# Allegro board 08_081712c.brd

Outline 415.29 x 196.85 mm; copper layers: TOP, L2_GND, L3_SIG, L4_GND, L5_PWR, L6_PWR, L7_GND, L8_SIG, L9_GND, BOTTOM. Coordinates in mm from the lower left corner of the outline.
Outline path: rectangle 0,0 415.29,196.85

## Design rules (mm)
constraint set DEFAULT: min track width 0.127
net group _N2180: nets _N2180 _N2453
net group DP__N689: nets _N689 _N710
net group DP__N697: nets _N697 _N701
net group DP_A1N_FB: nets _N582 A1N_FB
net group DP_A2N_FB: nets _N588 A2N_FB
net group DP_A3N_FB: nets _N570 A3N_FB
net group DP_A4N_FB: nets _N696 A4N_FB
net group DP_A5N_FB: nets _N702 A5N_FB
net group DP_A6N_FB: nets _N708 A6N_FB
net group DP_A7N_FB: nets _N690 A7N_FB
net group DP_AIN1_BUF: nets _N558 _N560
net group DP_AIN2_BUF: nets _N556 _N563
net group DP_AIN3_BUF: nets _N552 _N555
net group DP_AIN4_BUF: nets _N677 _N679
net group DP_AIN4N_BUFFERED: nets AIN4N_BUFFERED AIN4P_BUFFERED
net group DP_AIN5_BUF: nets AIN5N_BUFFERED AIN5P_BUFFERED
net group DP_AIN6_BUF: nets AIN6N_BUFFERED AIN6P_BUFFERED
net group DP_AIN7_BUF: nets AIN7N_BUFFERED AIN7P_BUFFERED
net group DP_MDI_0: nets MDI_0_N MDI_0_P
net group DP_MDI_1: nets MDI_1_N MDI_1_P
net group DP_MDI_2: nets MDI_2_N MDI_2_P
net group DP_MDI_3: nets MDI_3_N MDI_3_P
net group USB: nets E70_USBDM E70_USBDP
net group DP_AIN_BUF: nets _N561 _N566 _N569 _N572 _N575 _N584 _N587 _N590 _N672 _N674 _N675 _N676 _N678 _N680 _N681 _N682 _N683 _N686 _N692 _N695 _N704 _N707 _N1396 _N1399 _N1402 _N1405 _N1408 _N1410 _N1414 AIN1N AIN1N_BUFFERED AIN1P_BUFFERED AIN2N AIN2N_BUFFERED AIN2P_BUFFERED AIN3N AIN3N_BUFFERED AIN3P_BUFFERED AIN4N
net group ETH0-RX: nets ETH0_RXCTL_CRS_SOM_A ETH0_RXD0_SOM_A ETH0_RXD1_SOM_A ETH0_RXD2_SOM_A ETH0_RXD3_SOM_A
net group ETH0-TX: nets ETH0_TXCLK_SOM_A ETH0_TXD0_SOM_A ETH0_TXD1_SOM_A ETH0_TXD2_SOM_A ETH0_TXD3_SOM_A ETH0_TXEN_SOM_A
net group ETH1-TX: nets ETH1_TXCLK_SOM_B ETH1_TXD0_SOM_B ETH1_TXD2_SOM_B ETH1_TXD3_SOM_B ETH1_TXEN_SOM_B
net group ETH-A: nets _N13 _N14 _N16 _N17 _N18 _N19
net group ETH-B: nets _N43 _N44 _N46 _N47 _N48 _N49
net group JTAG1: nets JTAG_TCK_CONN JTAG_TDI_CONN JTAG_TMS_CONN JTAG_TRST_N_CONN
net group JTAG2: nets JTAG_EMU_CONN* JTAG_PD_CONN JTAG_TDO_CONN
net group JTAG3: nets JTAG_TCK JTAG_TDI JTAG_TMS JTAG_TRST_N
net group JTAG4: nets JTAG_EMU* JTAG_PD JTAG_TDO
net group JTG0: nets JTG0_TCK/SWCLK_LOCAL JTG0_TDI_LOCAL JTG0_TDO_LOCAL JTG0_TMS/SWDIO_LOCAL
net group LINKPORT-B: nets LINKPORT0_ACK_SOM_B LINKPORT0_CLK_SOM_B LINKPORT0_D0_SOM_B LINKPORT0_D1_SOM_B LINKPORT0_D2_SOM_B LINKPORT0_D3_SOM_B LINKPORT1_ACK_SOM_B LINKPORT1_CLK_SOM_B LINKPORT1_D0_SOM_B LINKPORT1_D1_SOM_B LINKPORT1_D2_SOM_B LINKPORT1_D3_SOM_B
net group LINKPORTA: nets LINKPORT0_ACK_SOM_A LINKPORT0_CLK_SOM_A LINKPORT0_D0_SOM_A LINKPORT0_D1_SOM_A LINKPORT0_D2_SOM_A LINKPORT0_D3_SOM_A LINKPORT1_ACK_SOM_A LINKPORT1_CLK_SOM_A LINKPORT1_D0_SOM_A LINKPORT1_D1_SOM_A LINKPORT1_D2_SOM_A LINKPORT1_D3_SOM_A
net group XSPI-0: nets _N1910 _N1911 _N1912 _N1913 _N1914 _N1915 _N1916 _N1917 _N1918 _N1919 _N1920 _N1921 _N1922

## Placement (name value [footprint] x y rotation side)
A1  ADA4610-1ARJZ  [SOT23-5L]  287.66 123.95 90 top
A2  ADA4610-1ARJZ  [SOT23-5L]  209.93 123.95 90 top
C1  1uF  [C0402]  163.96 24.38 270 bottom
C2  1uF  [C0402]  162.94 24.38 270 bottom
C3  1uF  [C0402]  290.96 24.38 270 bottom
C4  1uF  [C0402]  289.94 24.38 270 bottom
C5  0.01UF  [C0402]  163.45 31.37 90 bottom
C6  0.01UF  [C0402]  290.45 31.37 90 bottom
C7  0.01UF  [C0402]  224.79 41.4 0 bottom
C8  0.01uF  [C0402]  140.08 90.74 90 top
C9  0.01uF  [C0402]  213.49 62.42 90 top
C10  0.1UF  [C0402]  34.29 113.47 270 top
C11  0.1UF  [C0402]  262.25 118.55 270 top
C12  0.01UF  [C0402]  35.43 113.47 270 top
C13  0.01UF  [C0402]  263.4 118.55 270 top
C14  0.1uF  [C0402]  104.9 89.24 0 bottom
C15  0.1uF  [C0402]  109.6 83.59 90 bottom
C16  0.1uF  [C0402]  103.76 84.1 270 top
C17  0.1UF  [C0402]  147.57 38.23 270 bottom
C18  0.1UF  [C0402]  139.19 43.44 180 top
C19  0.01UF  [C0402]  134.24 45.21 0 top
C20  0.1UF  [C0402]  136.28 45.81 270 top
C21  0.1UF  [C0402]  133.22 38.23 180 bottom
C22  0.1UF  [C0402]  139.19 44.45 180 top
C23  0.1UF  [C0402]  211.84 89.79 0 top
C24  0.1UF  [C0402]  276.23 81.85 270 bottom
C25  0.01UF  [C0402]  133.22 39.25 180 bottom
C26  0.1UF  [C0402]  239.65 91.57 0 top
C27  0.01UF  [C0402]  139.83 39.25 0 bottom
C28  1uF  [C0805]  147.05 42 270 top
C29  1uF  [C0805]  147.05 47.84 270 top
C30  4.7uF  [C0603]  145.29 47.84 270 top
C31  4.7uF  [C0603]  145.29 42 270 top
C32  0.1UF  [C0402]  139.83 48.64 0 bottom
C33  0.1UF  [C0402]  133.22 48.64 180 bottom
C34  0.01UF  [C0402]  125.99 41.24 270 bottom
C35  0.01UF  [C0402]  133.22 47.63 180 bottom
C36  1uF  [C0805]  147.05 34.25 270 top
C37  0.1UF  [C0402]  127.13 21.27 180 top
C38  4.7uF  [C0603]  145.29 34.25 270 top
C39  0.1UF  [C0402]  127.13 23.81 180 top
C40  0.1UF  [C0402]  145.86 23.81 0 top
C41  0.1UF  [C0402]  145.86 21.27 0 top
C42  0.01UF  [C0402]  139.83 47.63 0 bottom
C43  0.1UF  [C0402]  274.57 38.23 270 bottom
C44  0.1UF  [C0402]  266.19 44.45 180 top
C45  0.01UF  [C0402]  264.29 45.81 270 top
C46  0.1UF  [C0402]  266.19 43.44 180 top
C47  0.1UF  [C0402]  266.83 38.23 0 bottom
C48  0.1UF  [C0402]  263.28 45.81 270 top
C49  0.1UF  [C0402]  260.22 38.23 180 bottom
C50  0.01UF  [C0402]  261.24 45.21 0 top
C51  0.01UF  [C0402]  266.83 39.25 0 bottom
C52  0.01UF  [C0402]  261.24 44.19 0 top
C53  0.01UF  [C0402]  260.22 39.25 180 bottom
C54  1uF  [C0805]  274.05 42 270 top
C55  1uF  [C0805]  274.05 47.84 270 top
C56  4.7uF  [C0603]  272.29 47.84 270 top
C57  4.7uF  [C0603]  272.29 42 270 top
C58  0.1UF  [C0402]  266.83 48.64 0 bottom
C59  0.1UF  [C0402]  260.22 48.64 180 bottom
C60  0.01UF  [C0402]  266.83 47.63 0 bottom
C61  0.01UF  [C0402]  260.22 47.63 180 bottom
C62  1uF  [C0805]  274.05 34.25 270 top
C63  0.1UF  [C0402]  272.86 21.27 0 top
C64  4.7uF  [C0603]  272.29 34.25 270 top
C65  0.1UF  [C0402]  272.86 23.81 0 top
C66  0.1UF  [C0402]  254.13 21.27 180 top
C67  0.1UF  [C0402]  254.13 23.81 180 top
C68  0.01UF  [C0402]  252.99 41.24 270 bottom
C69  4.7uF  [C0805H60]  218.06 82.8 90 bottom
C70  4.7uF  [C0805H60]  217.3 71.63 180 bottom
C71  4.7uF  [C0805H60]  221.36 71.63 0 bottom
C72  0.1UF  [C0402]  239.65 99.06 0 top
C73  0.1UF  [C0402]  239.65 84.45 0 top
C74  0.1UF  [C0402]  306.12 105.4 180 bottom
C75  0.1UF  [C0402]  228.39 105.4 180 bottom
C76  0.1UF  [C0402]  185.93 128.09 90 top
C77  0.1UF  [C0402]  305.31 112.27 180 top
C78  0.1UF  [C0402]  227.58 112.27 180 top
C79  0.1UF  [C0402]  296.29 118.36 270 top
C80  0.1UF  [C0402]  218.57 118.36 270 top
C81  10uF  [C0805H55]  294.64 117.73 270 top
C82  10uF  [C0805H55]  216.92 117.73 270 top
C83  390pF  [C0402]  293.62 122.66 180 top
C84  390pF  [C0402]  215.9 122.66 180 top
C85  0.1UF  [C0402]  296.16 122.17 270 top
C86  0.1UF  [C0402]  220.73 116.33 180 top
C87  5600pF  [C0402]  295.15 123.19 90 top
C88  5600pF  [C0402]  217.42 123.19 90 top
C89  10uF  [C0805H55]  304.93 127.51 0 top
C90  10uF  [C0805H55]  227.2 127.51 0 top
C91  0.1UF  [C0402]  305.31 110.62 180 top
C92  0.1UF  [C0402]  227.58 110.62 180 top
C93  0.1UF  [C0402]  298.45 116.33 180 top
C94  0.1UF  [C0402]  220.73 117.35 180 top
C95  0.1UF  [C0402]  296.16 125.35 90 top
C96  0.1UF  [C0402]  218.44 125.35 90 top
C97  0.1UF  [C0402]  298.96 112.39 180 top
C98  0.1UF  [C0402]  226.57 125.98 0 top
C99  10uF  [C0805H55]  294.64 126.11 90 top
C100  10uF  [C0805H55]  216.92 126.11 90 top
C101  0.1UF  [C0402]  297.69 125.98 180 top
C102  0.1UF  [C0402]  219.96 125.98 180 top
C103  47uF  [C1210H110]  291.85 126.75 90 top
C104  47uF  [C1210H110]  214.12 126.75 90 top
C105  0.1UF  [C0402]  298.45 117.35 180 top
C106  0.1UF  [C0402]  218.44 122.17 270 top
C107  0.1UF  [C0402]  304.29 125.98 0 top
C108  0.1UF  [C0402]  221.23 112.39 180 top
C109  0.01UF  [C0402]  284.73 123.44 90 top
C110  0.01UF  [C0402]  207.01 123.44 90 top
C111  0.1uF  [C0402]  325.25 145.16 180 top
C112  0.1uF  [C0402]  306.2 145.16 180 top
C113  10UF  [CPLSMSQ169H217]  335.79 159.51 270 top
C114  10UF  [CPLSMSQ169H217]  316.74 159.51 270 top
C115  10UF  [CPLSMSQ169H217]  324.87 159.51 270 top
C116  10UF  [CPLSMSQ169H217]  305.82 159.51 270 top
C117  330pF  [C0603]  337.57 146.3 270 top
C118  330pF  [C0603]  323.09 147.57 270 top
C119  330pF  [C0603]  318.52 146.3 270 top
C120  330pF  [C0603]  304.04 147.57 270 top
C121  10UF  [CPLSMSQ169H217]  334.39 140.34 270 top
C122  10UF  [CPLSMSQ169H217]  326.26 140.34 270 top
C123  10UF  [CPLSMSQ169H217]  315.34 140.34 270 top
C124  10UF  [CPLSMSQ169H217]  307.21 140.34 270 top
C125  0.1uF  [C0402]  285.62 145.16 180 top
C126  0.1uF  [C0402]  266.57 145.16 180 top
C127  10UF  [CPLSMSQ169H217]  296.16 159.51 270 top
C128  10UF  [CPLSMSQ169H217]  277.11 159.51 270 top
C129  10UF  [CPLSMSQ169H217]  285.24 159.51 270 top
C130  10UF  [CPLSMSQ169H217]  266.19 159.51 270 top
C131  330pF  [C0603]  297.94 146.3 270 top
C132  330pF  [C0603]  283.46 147.57 270 top
C133  330pF  [C0603]  278.89 146.3 270 top
C134  330pF  [C0603]  264.41 147.57 270 top
C135  10UF  [CPLSMSQ169H217]  294.77 140.34 270 top
C136  10UF  [CPLSMSQ169H217]  286.64 140.34 270 top
C137  10UF  [CPLSMSQ169H217]  275.72 140.34 270 top
C138  10UF  [CPLSMSQ169H217]  267.59 140.34 270 top
C139  0.1uF  [C0402]  247.52 145.16 180 top
C140  0.1uF  [C0402]  228.47 145.16 180 top
C141  10UF  [CPLSMSQ169H217]  258.06 159.51 270 top
C142  10UF  [CPLSMSQ169H217]  239.01 159.51 270 top
C143  10UF  [CPLSMSQ169H217]  247.14 159.51 270 top
C144  10UF  [CPLSMSQ169H217]  228.09 159.51 270 top
C145  330pF  [C0603]  259.84 146.3 270 top
C146  330pF  [C0603]  245.36 147.57 270 top
C147  330pF  [C0603]  240.79 146.3 270 top
C148  330pF  [C0603]  226.31 147.57 270 top
C149  10UF  [CPLSMSQ169H217]  256.67 140.34 270 top
C150  10UF  [CPLSMSQ169H217]  248.54 140.34 270 top
C151  10UF  [CPLSMSQ169H217]  237.62 140.34 270 top
C152  10UF  [CPLSMSQ169H217]  229.49 140.34 270 top
C153  0.1uF  [C0402]  207.9 145.16 180 top
C154  0.1uF  [C0402]  188.85 145.16 180 top
C155  10UF  [CPLSMSQ169H217]  218.44 159.51 270 top
C156  10UF  [CPLSMSQ169H217]  199.39 159.51 270 top
C157  10UF  [CPLSMSQ169H217]  207.52 159.51 270 top
C158  10UF  [CPLSMSQ169H217]  188.47 159.51 270 top
C159  330pF  [C0603]  220.22 146.3 270 top
C160  330pF  [C0603]  205.74 147.57 270 top
C161  330pF  [C0603]  201.17 146.3 270 top
C162  330pF  [C0603]  186.69 147.57 270 top
C163  10UF  [CPLSMSQ169H217]  217.04 140.34 270 top
C164  10UF  [CPLSMSQ169H217]  208.91 140.34 270 top
C165  10UF  [CPLSMSQ169H217]  197.99 140.34 270 top
C166  10UF  [CPLSMSQ169H217]  189.86 140.34 270 top
C167  0.22uF  [C0805H53]  34.8 17.32 270 top
C168  0.1UF  [C0402]  112.46 103.1 180 top
C169  0.1UF  [C0402]  121.09 103.1 0 bottom
C170  0.1UF  [C0402]  123.7 103.1 180 top
C171  0.1UF  [C0402]  121.09 104.88 0 bottom
C172  0.1UF  [C0402]  112.46 104.88 180 top
C173  0.1UF  [C0402]  123.7 104.88 180 top
C174  390pF  [C0402]  97.92 118.11 270 top
C175  0.1UF  [C0402]  96.39 117.75 180 top
C176  5600pF  [C0402]  96.39 118.77 180 top
C177  10uF  [C0805H53]  99.95 106.68 270 bottom
C178  0.1UF  [C0402]  100.08 109.98 90 top
C179  0.1UF  [C0402]  102.36 109.98 90 top
C180  10uF  [C0805H53]  102.49 106.68 270 bottom
C181  0.1UF  [C0402]  114.81 132.33 90 top
C182  10uF  [C0805H53]  115.95 129.79 270 bottom
C183  0.1UF  [C0402]  113.16 132.33 90 top
C184  10uF  [C0805H53]  113.41 113.66 90 bottom
C185  10uF  [C0805H53]  118.62 120.14 270 bottom
C186  10uF  [C0805H53]  113.54 129.79 270 bottom
C187  10uF  [C0805H53]  97.79 120.02 270 bottom
C188  0.47uF  [C0603]  98.3 130.68 90 top
C189  10uF  [C0805H53]  103.76 113.66 90 bottom
C190  0.47uF  [C0603]  118.75 128.27 180 top
C191  0.47uF  [C0603]  117.86 130.68 90 top
C192  0.1UF  [C0402]  118.49 126.62 0 top
C193  0.47uF  [C0603]  97.41 128.27 0 top
C194  0.1UF  [C0402]  97.66 126.62 180 top
C195  0.1UF  [C0402]  114.43 112.27 0 top
C196  0.1UF  [C0402]  118.62 120.15 270 top
C197  0.1UF  [C0402]  104.78 112.14 0 top
C198  0.1UF  [C0402]  97.92 120.02 270 top
C199  2700pF  [C0805]  135.51 125.93 270 top
C200  2700pF  [C0805]  135.51 129.74 90 top
C201  2700pF  [C0805]  135.51 134.57 270 top
C202  2700pF  [C0805]  135.51 138.38 90 top
C203  2700pF  [C0805]  135.51 108.66 270 top
C204  2700pF  [C0805]  135.51 112.47 90 top
C205  2700pF  [C0805]  135.51 117.3 270 top
C206  2700pF  [C0805]  135.51 121.11 90 top
C207  10uF  [C2312]  142.75 125.68 0 top
C208  10uF  [C2312]  142.75 130 0 top
C209  10uF  [C2312]  142.75 134.32 0 top
C210  10uF  [C2312]  142.75 138.63 0 top
C211  10uF  [C2312]  142.75 108.41 0 top
C212  10uF  [C2312]  142.75 112.73 0 top
C213  10uF  [C2312]  142.75 117.04 0 top
C214  10uF  [C2312]  142.75 121.36 0 top
C215  2700pF  [C0805]  122.29 149.86 0 top
C216  2700pF  [C0805]  118.48 149.86 180 top
C217  2700pF  [C0805]  113.65 149.86 0 top
C218  2700pF  [C0805]  109.84 149.86 180 top
C219  2700pF  [C0805]  139.56 149.86 0 top
C220  2700pF  [C0805]  135.75 149.86 180 top
C221  2700pF  [C0805]  130.93 149.86 0 top
C222  2700pF  [C0805]  127.12 149.86 180 top
C223  10uF  [C2312]  122.54 157.1 90 top
C224  10uF  [C2312]  118.23 157.1 90 top
C225  10uF  [C2312]  113.91 157.1 90 top
C226  10uF  [C2312]  109.59 157.1 90 top
C227  10uF  [C2312]  139.82 157.1 90 top
C228  10uF  [C2312]  135.5 157.1 90 top
C229  10uF  [C2312]  131.18 157.1 90 top
C230  10uF  [C2312]  126.86 157.1 90 top
C231  2700pF  [C0805]  87.75 149.86 0 top
C232  2700pF  [C0805]  83.94 149.86 180 top
C233  2700pF  [C0805]  79.11 149.86 0 top
C234  2700pF  [C0805]  75.3 149.86 180 top
C235  2700pF  [C0805]  105.02 149.86 0 top
C236  2700pF  [C0805]  101.21 149.86 180 top
C237  2700pF  [C0805]  96.38 149.86 0 top
C238  2700pF  [C0805]  92.57 149.86 180 top
C239  10uF  [C2312]  88 157.1 90 top
C240  10uF  [C2312]  83.68 157.1 90 top
C241  10uF  [C2312]  79.36 157.1 90 top
C242  10uF  [C2312]  75.05 157.1 90 top
C243  10uF  [C2312]  105.27 157.1 90 top
C244  10uF  [C2312]  100.95 157.1 90 top
C245  10uF  [C2312]  96.64 157.1 90 top
C246  10uF  [C2312]  92.32 157.1 90 top
C247  2700pF  [C0805]  80.64 138.38 90 top
C248  2700pF  [C0805]  80.64 134.57 270 top
C249  2700pF  [C0805]  80.64 129.74 90 top
C250  2700pF  [C0805]  80.64 125.93 270 top
C251  10uF  [C2312]  73.41 138.63 180 top
C252  10uF  [C2312]  73.41 134.32 180 top
C253  10uF  [C2312]  73.41 130 180 top
C254  10uF  [C2312]  73.41 125.68 180 top
C255  2700pF  [C0805]  80.64 121.11 90 top
C256  2700pF  [C0805]  80.64 117.3 270 top
C257  2700pF  [C0805]  80.64 112.47 90 top
C258  2700pF  [C0805]  80.64 108.66 270 top
C259  10uF  [C2312]  73.41 121.36 180 top
C260  10uF  [C2312]  73.41 117.04 180 top
C261  10uF  [C2312]  73.41 112.73 180 top
C262  10uF  [C2312]  73.41 108.41 180 top
C263  0.1UF  [C0402]  298.96 110.62 180 top
C264  0.1UF  [C0402]  296.08 105.4 180 bottom
C265  0.1UF  [C0402]  221.23 110.62 180 top
C266  0.1UF  [C0402]  218.36 105.4 180 bottom
C267  0.1UF  [C0402]  115.78 94.12 0 bottom
C268  0.1UF  [C0402]  133.3 94.12 0 bottom
C269  0.1UF  [C0402]  119.17 99.68 180 bottom
C270  0.01uF  [C0402]  92.58 37.97 180 top
C271  0.01uF  [C0402]  78.49 37.97 180 top
C272  0.1UF  [C0402]  92.58 38.99 180 top
C273  0.1UF  [C0402]  78.49 38.99 180 top
C274  0.01uF  [C0402]  90.04 24.38 180 top
C275  0.01uF  [C0402]  75.95 24.38 180 top
C276  0.1UF  [C0402]  90.04 23.24 180 top
C277  0.1UF  [C0402]  75.95 23.24 180 top
C278  0.033uF  [C0402]  87.38 22.35 270 bottom
C279  0.033uF  [C0402]  73.28 22.35 270 bottom
C280  0.01uF  [C0402]  341.4 37.95 180 top
C281  0.01uF  [C0402]  355.5 37.95 180 top
C282  0.1UF  [C0402]  341.4 38.96 180 top
C283  0.1UF  [C0402]  355.5 38.96 180 top
C284  0.01uF  [C0402]  338.86 24.36 180 top
C285  0.01uF  [C0402]  352.96 24.36 180 top
C286  0.1UF  [C0402]  338.86 23.22 180 top
C287  0.1UF  [C0402]  352.96 23.22 180 top
C288  0.033uF  [C0402]  350.29 22.33 270 bottom
C289  0.033uF  [C0402]  336.19 22.33 270 bottom
C290  0.1UF  [C0402]  128.4 78.93 0 bottom
C291  0.1UF  [C0402]  144.91 78.93 0 bottom
C292  0.1UF  [C0402]  255.4 78.93 0 bottom
C293  0.1UF  [C0402]  271.91 78.93 0 bottom
C294  1uF  [C0805H53]  393.7 152.78 180 top
C295  0.1UF  [C0402]  11.18 34.16 180 bottom
C296  1uF  [C0805H53]  393.7 107.19 180 top
C297  0.1UF  [C0402]  395.35 154.81 0 top
C298  1000pF  [C1206]  336.55 188.21 270 top
C299  0.1UF  [C0402]  395.35 109.22 0 top
C300  0.01UF  [C0805-2]  403.61 104.9 270 top
C301  0.01UF  [C0805-2]  403.61 150.5 270 top
C302  10uF  [C1210]  370.46 183.77 270 top
C303  10pF  [C0402]  406.91 105.28 90 top
C304  10pF  [C0402]  406.91 150.88 90 top
C305  22uF  [C1210H106]  390.02 116.33 90 top
C306  22uF  [C1210H106]  390.02 161.93 90 top
C307  4.7uF  [C1206H71-2]  403.73 110.49 90 top
C308  4.7uF  [C1206H71-2]  403.73 156.08 90 top
C309  1uF  [C0805H53]  393.7 130.05 180 top
C310  1uF  [C0805H53]  393.7 173.23 180 top
C311  0.1UF  [C0402]  395.35 132.08 0 top
C312  0.1UF  [C0402]  395.35 175.26 0 top
C313  0.01UF  [C0805-2]  403.61 127.76 270 top
C314  0.01UF  [C0805-2]  403.61 170.94 270 top
C315  10pF  [C0402]  406.91 128.14 90 top
C316  10pF  [C0402]  406.91 171.32 90 top
C317  22uF  [C1210H106]  390.02 139.19 90 top
C318  22uF  [C1210H106]  390.02 182.37 90 top
C319  4.7uF  [C1206H71-2]  403.73 133.35 90 top
C320  4.7uF  [C1206H71-2]  403.73 176.53 90 top
C321  0.1uF  [C0402]  193.55 21.53 0 top
C322  0.1uF  [C0402]  201.04 27.24 0 top
C323  10pF  [C0402]  209.42 16.32 0 top
C324  0.1uF  [C0402]  211.2 22.67 0 bottom
C325  0.01uF  [C0201]  206.91 36.89 0 top
C326  0.1uF  [C0402]  207.01 38.04 0 top
C327  0.1uF  [C0402]  201.42 17.84 180 bottom
C328  0.1uF  [C0402]  201.42 18.86 180 bottom
C329  0.1uF  [C0402]  211.73 18.22 270 bottom
C330  2.2uF  [C0402]  201.42 19.88 180 bottom
C331  0.1uF  [C0402]  207.45 24.1 90 bottom
C332  0.1uF  [C0402]  206.63 21.02 180 bottom
C333  12pF  [C0402]  213.04 15.11 315 top
C334  0.1uF  [C0402]  211.73 20.26 90 bottom
C335  12pF  [C0402]  210.43 24.96 0 top
C336  0.1uF  [C0402]  220.22 9.84 0 top
C337  0.1uF  [C0402]  201.42 20.89 180 bottom
C338  12pF  [C0402]  207.26 24.96 180 top
C339  1uF  [C0402]  220.22 8.83 0 top
C340  0.1uF  [C0402]  204.47 17.46 180 bottom
C341  1uF  [C0402]  220.22 7.81 0 top
C342  12pF  [C0402]  213.36 21.02 45 top
C343  22uF  [C0603]  220.22 6.54 0 top
C344  1uF  [C0402]  224.03 13.02 0 top
C345  0.1uF  [C0402]  203.71 12 180 bottom
C346  0.1uF  [C0402]  206.63 20 180 bottom
C347  330pF  [C0201]  218.31 13.59 180 top
C348  0.1uF  [C0402]  209.68 16.95 270 bottom
C349  0.1uF  [C0402]  210.69 16.95 270 bottom
C350  0.1uF  [C0402]  208.66 16.95 270 bottom
C351  0.22uF  [C0402]  224.03 10.99 0 top
C352  0.1uF  [C0402]  204.34 15.3 180 bottom
C353  0.01uF  [C0402]  193.55 26.86 0 top
C354  0.1uF  [C0402]  205.99 23.65 180 bottom
C355  10uF  [C0603]  220.6 15.05 0 top
C356  22uF  [C0603]  229.36 7.18 0 top
C357  0.1uF  [C0402]  211.2 23.69 0 bottom
C358  0.1uF  [C0402]  204.34 16.32 180 bottom
C359  1UF  [C0402]  232.16 19.24 0 top
C360  10uF  [C0402]  232.03 24.07 0 top
C361  1UF  [C0402]  232.03 23.05 0 top
C362  0.1UF  [C0402]  232.03 22.03 0 top
C363  0.1UF  [C0402]  218.95 23.94 180 top
C364  0.1UF  [C0402]  195.2 36.77 270 bottom
C365  0.1UF  [C0402]  195.2 38.8 90 bottom
C366  0.1UF  [C0402]  220.98 23.94 0 top
C367  0.1UF  [C0402]  211.45 33.34 270 top
C368  0.1UF  [C0402]  211.45 35.37 90 top
C369  0.1UF  [C0402]  384.56 23.11 0 top
C370  0.1UF  [C0402]  149.22 81.85 270 bottom
C371  0.1UF  [C0402]  136.78 87.06 0 bottom
C372  0.1UF  [C0402]  263.78 87.06 0 bottom
C373  0.1UF  [C0402]  15.24 18.9 0 bottom
C374  0.1UF  [C0402]  16.89 21.34 0 top
C375  0.1UF  [C0402]  12.7 13.06 0 bottom
C376  0.1UF  [C0402]  9.4 24.89 180 top
C377  0.1UF  [C0402]  16.89 23.11 0 top
C378  0.1UF  [C0402]  382.91 18.9 0 bottom
C379  0.1UF  [C0402]  380.37 13.06 0 bottom
C380  0.1UF  [C0402]  384.56 21.34 0 top
C381  0.1UF  [C0402]  377.06 24.89 180 top
C382  0.1UF  [C0402]  378.84 34.16 180 bottom
C383  0.01uF  [C0402]  248.67 26.04 90 bottom
C384  0.22uF  [C0805H53]  37.34 17.32 270 top
C385  0.1UF  [C0402]  30.61 23.16 90 top
C386  0.1UF  [C0402]  27.3 19.99 270 top
C387  0.1UF  [C0402]  33.78 27.23 90 top
C388  0.01UF  [C0402]  134.24 44.19 0 top
C389  0.01UF  [C0402]  137.29 45.81 270 top
C390  0.1UF  [C0402]  139.83 38.23 0 bottom
C391  0.22uF  [C0805H53]  402.46 17.32 270 top
C392  0.22uF  [C0805H53]  405 17.32 270 top
C393  0.1UF  [C0402]  398.27 23.16 90 top
C394  0.01uF  [C0402]  240.92 25.53 180 bottom
C395  2.2NF  [C0402]  233.15 27.61 180 top
C396  0.01uF  [C0402]  236.45 30.66 180 top
C397  0.1UF  [C0402]  394.97 19.99 270 top
C398  0.1UF  [C0402]  401.45 27.23 90 top
C399  2700pF  [C0805]  137.67 110.57 90 top
C400  2700pF  [C0805]  137.67 119.2 90 top
C401  2700pF  [C0805]  137.67 127.84 90 top
C402  2700pF  [C0805]  137.67 136.47 90 top
C403  2700pF  [C0805]  137.66 152.02 180 top
C404  2700pF  [C0805]  129.02 152.02 180 top
C405  2700pF  [C0805]  120.39 152.02 180 top
C406  2700pF  [C0805]  111.75 152.02 180 top
C407  2700pF  [C0805]  103.11 152.02 180 top
C408  2700pF  [C0805]  94.48 152.02 180 top
C409  2700pF  [C0805]  85.84 152.02 180 top
C410  2700pF  [C0805]  77.21 152.02 180 top
C411  2700pF  [C0805]  78.49 136.47 270 top
C412  2700pF  [C0805]  78.49 127.84 270 top
C413  2700pF  [C0805]  78.49 119.2 270 top
C414  2700pF  [C0805]  78.49 110.57 270 top
C415  10uF  [C1210]  357.38 183.64 90 top
C416  1uF  [C0805H53]  108.2 58.55 0 bottom
C417  0.1UF  [C0402]  106.55 60.58 180 bottom
C418  0.01UF  [C0805-2]  98.3 56.26 270 bottom
C419  10pF  [C0402]  95 56.64 90 bottom
C420  22uF  [C1210H106]  109.6 69.34 0 bottom
C421  4.7uF  [C1206H71-2]  98.17 61.85 90 bottom
C422  1uF  [C0805H53]  235.2 58.55 0 bottom
C423  0.1UF  [C0402]  233.55 60.58 180 bottom
C424  0.01UF  [C0805-2]  225.3 56.26 270 bottom
C425  10pF  [C0402]  222 56.64 90 bottom
C426  22uF  [C1210H106]  236.47 69.09 0 bottom
C427  4.7uF  [C1206H71-2]  225.17 61.85 90 bottom
C428  0.1UF  [C0402]  187.83 81.66 180 bottom
C429  0.1UF  [C0402]  187.83 80.14 180 bottom
C430  0.1UF  [C0402]  187.83 85.6 180 top
C431  0.1UF  [C0402]  187.83 87.12 180 top
C432  0.1UF  [C0402]  182.84 123.88 0 top
C433  0.1UF  [C0402]  182.84 122.53 0 top
D1  SP0504SHTG  [SOT23_6]  139.19 31.8 270 bottom
D2  SP0504SHTG  [SOT23_6]  133.86 31.8 270 bottom
D3  SP0504SHTG  [SOT23_6]  266.19 31.8 270 bottom
D4  SP0504SHTG  [SOT23_6]  260.86 31.8 270 bottom
D5  PESD24VL2BT,215  [SOT23-M3]  83.54 8.13 270 bottom
D6  PESD24VL2BT,215  [SOT23-M3]  83.54 14.86 270 bottom
D7  PESD24VL2BT,215  [SOT23-M3]  346.46 8.1 270 bottom
D8  PESD24VL2BT,215  [SOT23-M3]  346.46 14.83 270 bottom
D9  MBRS540T3G  [SMC]  351.92 185.29 270 top
D10  MBRS540T3G  [SMC]  365.25 185.29 90 top
D11  MMSZ5246B-TP  [SOD123-2]  373.51 183.77 90 top
D12  598-8610-307F  [LED1210H28]  194.69 18.86 180 top
D13  ESDA25W5  [SC70-5_A]  207.64 13.65 0 bottom
DS1  5988E30107F  [LED0603]  153.8 85.03 270 top
DS2  5988E30107F  [LED0603]  156.34 85.03 270 top
DS3  5988E30107F  [LED0603]  158.88 85.03 270 top
DS4  5988E30107F  [LED0603]  280.8 85.03 270 top
DS5  5988E30107F  [LED0603]  283.34 85.03 270 top
DS6  5988E30107F  [LED0603]  285.88 85.03 270 top
DS7  5988E30107F  [LED0603]  24.51 103.25 90 top
DS8  5988E30107F  [LED0603]  26.04 103.25 90 top
DS9  5988E30107F  [LED0603]  27.56 103.25 90 top
DS10  5988E30107F  [LED0603]  29.08 103.25 90 top
DS11  5988E30107F  [LED0603]  30.61 103.25 90 top
DS12  5988E30107F  [LED0603]  32.13 103.25 90 top
DS13  5988E30107F  [LED0603]  252.48 108.33 90 top
DS14  5988E30107F  [LED0603]  254 108.33 90 top
DS15  5988E30107F  [LED0603]  255.52 108.33 90 top
DS16  5988E30107F  [LED0603]  257.05 108.33 90 top
DS17  5988E30107F  [LED0603]  258.57 108.33 90 top
DS18  5988E30107F  [LED0603]  260.1 108.33 90 top
DS19  5988E30107F  [LED0603]  130.94 90.61 0 top
DS20  TLMS1100-GS15  [LED0603]  197.61 27.75 270 top
DS21  CSL0901UT1C  [LED0603H50]  62.74 90.68 90 top
DS22  CSL0901UT1C  [LED0603H50]  378.08 90.68 90 top
DS23  SML-LX0805SRC-TR  [LED0805_A]  226.42 30.45 0 top
DS24  5988E30107F  [LED0603]  130.94 89.09 0 top
DS25  5988E30107F  [LED0603]  257.94 89.09 0 top
DS26  5988E30107F  [LED0603]  257.94 90.61 0 top
E3  47OHM  [L0402]  210.69 21.15 270 bottom
E4  470OHM  [L0402]  202.95 18.35 90 bottom
E5  470OHM  [L0402]  210.69 19.24 90 bottom
F1  3A  [F2920]  343.03 188.85 0 top
J1  PJRAS1X2S01AUX  [CNSWITCHCRAFTPJRAS1X2SXXXX]  27.3 12.5 0 top
J2  PJRAS1X2S01AUX  [CNSWITCHCRAFTPJRAS1X2SXXXX]  394.97 12.5 0 top
J4  LSS-150-01-L-DV-A-K  [CNSAMTECLSS-150-01-X-DV-A]  23.62 75.1 180 bottom
J5  LSS-150-01-L-DV-A-K  [CNSAMTECLSS-150-01-X-DV-A]  76.33 75.1 180 bottom
L1  2.2uH  [LSML208W216H122]  394.84 158.62 270 top
L2  4.7uH  [LSMSQ157H122]  359.41 188.72 0 top
L3  10NH  [L0402]  220.22 73.74 270 bottom
L4  10NH  [L0402]  218.44 73.74 270 bottom
L5  2.2uH  [LSML208W216H122]  394.84 113.03 270 top
L6  2.2uH  [LSML208W216H122]  394.84 135.89 270 top
L7  2.2uH  [LSML208W216H122]  394.84 179.07 270 top
L8  33UH  [LSMSQ118H47]  227.08 9.97 270 top
L9  2.2uH  [LSML208W216H122]  107.06 64.39 270 bottom
L10  2.2uH  [LSML208W216H122]  234.06 64.39 270 bottom
M1  FC6842135TR  [MC6842135TR]  11.43 10.9 180 top
M2  FC6842135TR  [MC6842135TR]  379.1 10.9 180 top
NOREF  -  [unnamed]  207.64 95.88 0 top
NOREF#2  -  [#2]  196.85 373.95 0 top
NOREF#3  -  [#2]  306.3 1.65 0 top
NOREF#4  -  [unnamed]  412.5 3.03 0 top
NOREF#5  -  [unnamed]  3.3 7.18 0 top
NOREF#6  -  [unnamed]  308.64 3.99 0 top
NOREF#7  -  [#2]  31.75 156.21 0 top
NOREF#8  -  [#2]  51.69 164.21 0 top
NOREF#9  -  [#2]  354.52 73.3 90 top
NOREF#10  -  [unnamed]  44.45 3.03 0 top
NOREF#11  -  [#2]  275.21 22.03 0 top
NOREF#12  -  [unnamed]  106.65 3.99 0 top
NOREF#13  -  [unnamed]  412.37 7.18 0 top
NOREF#14  -  [#2]  415.29 0 90 top
NOREF#15  -  [#2]  473.07 67.25 0 top
NOREF#16  -  [#2]  39.18 73.3 90 top
NOREF#17  -  [#2]  415.29 196.85 180 top
NOREF#18  -  [unnamed]  97.16 3.03 0 top
NOREF#19  -  [#2]  205.1 251.4 0 top
NOREF#20  -  [#2]  0 196.85 0 top
NOREF#21  -  [#2]  0 196.85 0 top
NOREF#22  -  [unnamed]  207.64 191.77 0 top
NOREF#23  -  [unnamed]  207.64 187.64 0 top
NOREF#24  -  [unnamed]  308.93 191.77 0 top
NOREF#25  -  [#2]  -156.84 -135.95 0 top
NOREF#26  -  [unnamed]  410.21 95.88 0 top
NOREF#27  -  [#2]  230.15 69.99 0 top
NOREF#28  -  [unnamed]  359.79 3.03 0 top
NOREF#29  -  [unnamed]  181.64 3.99 0 top
NOREF#30  -  [#2]  415.29 0 0 top
NOREF#31  -  [#2]  321.83 -19.87 0 top
NOREF#32  -  [unnamed]  5.08 191.77 0 top
NOREF#33  -  [#2]  58.92 19.84 0 top
NOREF#34  -  [#2]  -156.84 -135.95 0 top
NOREF#35  -  [unnamed]  410.21 191.77 0 top
NOREF#36  -  [unnamed]  106.36 95.88 0 top
NOREF#37  -  [#2]  233.65 3.99 0 top
NOREF#38  -  [#2]  0 0 0 top
NOREF#39  -  [#2]  0 196.85 270 top
NOREF#40  -  [unnamed]  5.08 95.88 0 top
NOREF#41  -  [unnamed]  3.04 3.17 0 top
NOREF#42  -  [#2]  415.29 0 90 top
NOREF#43  -  [#2]  106.65 3.99 0 top
NOREF#44  -  [unnamed]  371.08 3.17 0 top
NOREF#45  -  [unnamed]  106.36 191.77 0 top
NOREF#46  -  [#2]  3.04 3.17 0 top
NOREF#47  -  [#2]  407.23 73.3 90 top
NOREF#48  -  [#2]  -156.84 -135.95 0 top
NOREF#49  -  [#2]  0 0 0 top
NOREF#50  -  [unnamed]  318.38 3.17 0 top
NOREF#51  -  [#2]  0 0 0 top
NOREF#52  -  [#2]  3.04 3.17 0 top
NOREF#53  -  [#2]  20.7 156.46 0 top
NOREF#54  -  [unnamed]  308.93 95.88 0 top
NOREF#55  -  [#2]  91.88 73.3 90 top
NOREF#56  -  [unnamed]  55.74 3.17 0 top
NOREF#57  -  [unnamed]  233.65 3.99 0 top
NOREF#58  -  [#2]  24.77 134.94 0 top
NOREF#59  -  [unnamed]  412.37 7.18 180 bottom
NOREF#60  -  [unnamed]  3.3 7.18 180 bottom
NOREF#61  -  [unnamed]  207.64 187.64 180 bottom
P1  7499511440  [CNWURTH7499511440]  131.45 21.3 180 bottom
P2  7499511440  [CNWURTH7499511440]  258.45 21.3 180 bottom
P3  LSS-150-01-L-DV-A-K  [CNSAMTECLSS-150-01-X-DV-A]  338.96 75.1 180 bottom
P4  LSS-150-01-L-DV-A-K  [CNSAMTECLSS-150-01-X-DV-A]  391.67 75.1 180 bottom
P5  PBC08DAAN  [CNTHMHDR2X8L800W200H343_OE]  145.54 100.46 0 top
P6  PBC08DAAN  [CNTHMHDR2X8L800W200H343_OE]  272.54 100.46 0 top
P7  PJ-102A  [CNCUI-PJ-102A]  330.45 186.69 90 top
P8  SHF-105-01-L-D-TH-TR  [CNTHMHDR2X5L500W200H215]  207.77 67.63 180 top
P9  632723300011  [CNWURTH632723300011]  207.64 6 0 top
P10  M20-8770342  [CNHDR1X3H391]  227.2 21.65 90 top
P11  STX-4335-5BGP-S1  [CNKYCONSTX-4335-5BGP-S1]  125.09 188.06 180 top
P12  STX-4335-5BGP-S1  [CNKYCONSTX-4335-5BGP-S1]  156.84 188.06 180 top
P13  STX-4335-5BGP-S1  [CNKYCONSTX-4335-5BGP-S1]  188.59 188.06 180 top
P14  178-025-513R571  [CNNOR178-025-513R57X]  51.94 185.93 180 top
P15  STX-4335-5BGP-S1  [CNKYCONSTX-4335-5BGP-S1]  220.34 188.06 180 top
P16  747461-1  [CNAMP747461-1]  255.91 178.24 0 top
P17  61300311121  [CNHDR1X3H340]  371.48 173.99 270 top
P18  178-009-513R491  [CNNORCOMP_178-009-513R491]  81.92 10.92 0 top
P19  178-009-513R491  [CNNORCOMP_178-009-513R491]  344.83 10.9 0 top
P20  MTSW-120-07-S-S-240  [CNBERG1X20H340LD36]  48.26 87.25 270 top
P21  MTSW-120-07-S-S-240  [CNBERG1X20H340LD36]  51.69 38.99 90 top
P22  HTSW-106-07-G-S  [CNHDR1X6H343]  178.43 101.98 0 top
P23  HTSW-106-07-G-S  [CNHDR1X6H343]  322.33 101.98 0 top
P24  HTSW-106-07-G-S  [CNHDR1X6H343]  178.43 94.11 0 top
P25  HTSW-106-07-G-S  [CNHDR1X6H343]  322.33 94.11 0 top
P26  HTSW-106-07-G-S  [CNHDR1X6H343]  178.43 109.86 0 top
P27  HTSW-106-07-G-S  [CNHDR1X6H343]  322.33 109.86 0 top
P28  TSW-102-09-G-S  [CNHDR1X2H330]  195.58 24.07 180 top
P29  TSW-102-09-G-S  [CNHDR1X2H330]  200.53 29.65 0 top
P30  SHF-108-01-L-D-SM  [CNSMMHDR2X8L650W220H220]  68.83 85.85 180 top
P31  SHF-108-01-L-D-SM  [CNSMMHDR2X8L650W220H220]  384.18 85.85 180 top
P32  TSW-106-14-T-D  [CNHDR2X6H420LD35]  19.69 86.36 180 top
P33  TSW-106-14-T-D  [CNHDR2X6H420LD35]  335.03 86.36 180 top
P34  SHF-105-01-L-D-SM-TR  [CNHDR2X5H220]  194.56 11.24 0 top
P35  SHF-110-01-L-D-TH  [CNTHMHDR2X10L750W220H215]  210.85 79.31 180 top
P36  69157-102HLF  [CNBERG69157-102]  95.63 110.87 90 top
P37  TSW-106-14-T-D  [CNHDR2X6H420LD35]  88.27 45.72 0 top
P38  TSM-104-01-T-SV  [CNSM1X4H380]  157.61 79.69 0 top
P39  MTSW-120-07-S-S-240  [CNBERG1X20H340LD36]  363.6 87.25 270 top
P40  MTSW-120-07-S-S-240  [CNBERG1X20H340LD36]  367.03 38.99 90 top
P42  TSM-104-01-T-SV  [CNSM1X4H380]  284.61 79.69 0 top
PB1  ELUMOASAQ6C12  [SWSML1110W450H237]  170.31 10.67 90 bottom
PB2  ELUMOASAQ6C12  [SWSML1110W450H237]  156.59 10.67 90 bottom
PB3  ELUMOASAQ6C12  [SWSML1110W450H237]  297.31 10.67 90 bottom
PB4  ELUMOASAQ6C12  [SWSML1110W450H237]  283.59 10.67 90 bottom
Q1  FZT953TA  [SOT223-2]  102.36 104.27 180 top
R1  33  [R0402]  141.1 62.93 0 bottom
R2  3K  [R0402]  150.29 73.09 90 bottom
R3  3K  [R0402]  151.43 73.09 90 bottom
R4  3K  [R0402]  152.58 73.09 90 bottom
R5  3K  [R0402]  153.72 73.09 90 bottom
R6  3K  [R0402]  154.86 73.09 90 bottom
R7  3K  [R0402]  156.01 73.09 90 bottom
R8  33  [R0402]  268.1 62.93 0 bottom
R9  100  [R0402]  166.12 24.38 90 bottom
R10  100  [R0402]  160.78 24.38 90 bottom
R11  100  [R0402]  293.12 24.38 90 bottom
R12  100  [R0402]  287.78 24.38 90 bottom
R13  10K  [R0402]  165.02 24.38 90 bottom
R14  10K  [R0402]  161.87 24.38 90 bottom
R15  10K  [R0402]  292.02 24.38 90 bottom
R16  10K  [R0402]  288.87 24.38 90 bottom
R17  33  [R0402]  164.59 31.37 90 bottom
R18  33  [R0402]  162.31 31.37 90 bottom
R19  33  [R0402]  291.59 31.37 90 bottom
R20  33  [R0402]  289.31 31.37 90 bottom
R21  10K  [R0402]  224.79 42.51 180 bottom
R22  10K  [R0402]  224.79 44.46 0 bottom
R23  10  [R0402]  153.8 87.82 90 top
R24  10K  [R0402]  215.14 41.86 0 bottom
R25  10K  [R0402]  215.14 43.81 180 bottom
R26  10  [R0402]  156.34 87.82 90 top
R27  10  [R0402]  158.88 87.82 90 top
R28  10  [R0402]  280.8 87.82 90 top
R29  10  [R0402]  283.34 87.82 90 top
R30  10  [R0402]  285.88 87.82 90 top
R31  10K  [R0402]  34.29 110.93 90 top
R32  10K  [R0402]  262.25 116.01 90 top
R33  10K  [R0402]  103.89 91.31 180 bottom
R34  10K  [R0402]  99.44 91.31 180 bottom
R35  10K  [R0402]  98.68 83.31 180 bottom
R36  10K  [R0402]  101.09 89.75 270 bottom
R37  0  [R0402]  103.38 89.75 270 bottom
R38  0  [R0402]  99.95 89.75 270 bottom
R39  0  [R0402]  98.68 84.45 0 bottom
R40  33  [R0402]  102.23 89.75 270 bottom
R41  0  [R0402]  98.68 85.6 180 bottom
R42  0  [R0402]  110.11 86.32 0 bottom
R43  0  [R0402]  104.9 80.48 270 bottom
R44  0  [R0402]  106.05 80.48 270 bottom
R45  0  [R0402]  110.11 87.46 0 bottom
R46  0  [R0402]  106.43 89.75 90 bottom
R47  0  [R0402]  103.76 80.48 270 bottom
R48  0  [R0402]  110.11 85.18 0 bottom
R49  0  [R0402]  107.57 89.75 90 bottom
R50  10K  [R0402]  98.68 87.88 180 bottom
R51  10K  [R0402]  98.68 86.74 0 bottom
R52  10K  [R0402]  136.14 55.63 90 bottom
R53  10K  [R0402]  136.14 55.63 270 top
R54  10K  [R0402]  137.41 55.63 90 bottom
R55  10K  [R0402]  137.41 55.63 270 top
R56  33  [R0402]  141.35 41.53 180 bottom
R57  3.01K  [R0402]  141.35 40.39 180 bottom
R58  10K  [R0402]  129.54 50.74 90 bottom
R59  10K  [R0402]  129.54 50.74 270 top
R60  10K  [R0402]  130.68 50.74 90 bottom
R61  10K  [R0402]  130.68 50.74 270 top
R62  10K  [R0402]  129.16 41.85 180 bottom
R63  33  [R0402]  134.87 53.22 270 bottom
R64  33  [R0402]  133.6 53.22 270 bottom
R65  33  [R0402]  136.14 53.22 270 bottom
R66  10K  [R0402]  133.6 55.63 90 bottom
R67  10K  [R0402]  133.6 55.63 270 top
R68  100K  [R0402]  141.35 42.69 180 bottom
R69  33  [R0402]  130.68 48.33 270 bottom
R70  33  [R0402]  137.41 53.22 270 bottom
R71  10K  [R0402]  134.87 55.63 90 bottom
R72  10K  [R0402]  134.87 55.63 270 top
R73  33  [R0402]  129.54 48.33 270 bottom
R74  10K  [R0402]  129.16 45.09 180 bottom
R75  10K  [R0402]  129.16 45.09 0 top
R76  10K  [R0402]  129.16 44.01 180 bottom
R77  10K  [R0402]  129.16 44.01 0 top
R78  1.5K  [R0402]  129.16 40.77 0 bottom
R79  10K  [R0402]  129.16 39.37 180 bottom
R80  10K  [R0402]  129.16 39.37 0 top
R81  1.5K  [R0402]  129.16 42.93 0 bottom
R82  330  [R0402]  140.59 28.51 0 top
R83  330  [R0402]  132.46 28.51 180 top
R84  10K  [R0402]  263.14 55.63 90 bottom
R85  10K  [R0402]  263.14 55.63 270 top
R86  10K  [R0402]  264.41 55.63 90 bottom
R87  10K  [R0402]  264.41 55.63 270 top
R88  33  [R0402]  268.35 41.53 180 bottom
R89  3.01K  [R0402]  268.35 40.39 180 bottom
R90  10K  [R0402]  256.54 50.74 90 bottom
R91  10K  [R0402]  256.54 50.74 270 top
R92  10K  [R0402]  257.68 50.74 90 bottom
R93  10K  [R0402]  257.68 50.74 270 top
R94  10K  [R0402]  256.16 41.85 180 bottom
R95  33  [R0402]  261.87 53.22 270 bottom
R96  33  [R0402]  260.6 53.22 270 bottom
R97  33  [R0402]  263.14 53.22 270 bottom
R98  10K  [R0402]  260.6 55.63 90 bottom
R99  10K  [R0402]  260.6 55.63 270 top
R100  100K  [R0402]  268.35 42.69 180 bottom
R101  33  [R0402]  257.68 48.33 270 bottom
R102  33  [R0402]  264.41 53.22 270 bottom
R103  10K  [R0402]  261.87 55.63 90 bottom
R104  10K  [R0402]  261.87 55.63 270 top
R105  33  [R0402]  256.54 48.33 270 bottom
R106  10K  [R0402]  256.16 45.09 180 bottom
R107  10K  [R0402]  256.16 45.09 0 top
R108  10K  [R0402]  256.16 44.01 180 bottom
R109  10K  [R0402]  256.16 44.01 0 top
R110  1.5K  [R0402]  256.16 40.77 0 bottom
R111  10K  [R0402]  256.16 39.37 180 bottom
R112  10K  [R0402]  256.16 39.37 0 top
R113  1.5K  [R0402]  256.16 42.93 0 bottom
R114  330  [R0402]  267.59 28.51 0 top
R115  330  [R0402]  259.46 28.51 180 top
R116  40K  [R0603H18]  221.11 75.56 0 bottom
R117  50K  [R0603]  221.87 78.11 270 bottom
R118  40K  [R0603H18]  217.55 75.56 180 bottom
R119  50K  [R0603]  216.79 77.98 90 bottom
R120  3K  [R0402]  226 90.23 270 top
R121  10K  [R0402]  240.28 97.54 0 top
R122  10K  [R0402]  240.28 82.93 0 top
R123  33  [R0402]  306.32 108.46 90 top
R124  20K  [R0402]  307.47 108.46 270 top
R125  20K  [R0402]  229.74 108.46 270 top
R126  33  [R0402]  178.05 127.63 180 top
R127  3K  [R0402]  308.99 115.06 270 top
R128  3K  [R0402]  231.27 115.06 270 top
R129  3K  [R0402]  310.13 115.06 270 top
R130  3K  [R0402]  232.41 115.06 270 top
R131  10K  [R0402]  307.85 115.06 90 top
R132  10K  [R0402]  230.12 115.06 90 top
R133  100K  [R0402]  294.64 120.02 180 top
R134  100K  [R0402]  216.92 120.02 180 top
R135  0  [R0402]  294.64 121.08 0 top
R136  0  [R0402]  216.92 121.08 0 top
R137  100K  [R0402]  304.56 115.06 270 top
R138  100K  [R0402]  226.83 115.06 270 top
R139  100K  [R0402]  305.7 115.06 270 top
R140  100K  [R0402]  227.98 115.06 270 top
R141  33  [R0402]  301.13 115.06 270 top
R142  33  [R0402]  303.42 115.06 270 top
R143  33  [R0402]  223.41 115.06 270 top
R144  33  [R0402]  225.69 115.06 270 top
R145  33  [R0402]  299.99 115.06 270 top
R146  33  [R0402]  302.27 115.06 270 top
R147  33  [R0402]  222.26 115.06 270 top
R148  33  [R0402]  224.55 115.06 270 top
R149  3K  [R0402]  292.99 118.36 270 top
R150  3K  [R0402]  215.26 118.36 270 top
R151  1K  [R0402]  293.62 123.7 0 top
R152  1K  [R0402]  215.9 123.7 0 top
R153  49.9K  [R0402]  335.28 163.58 180 top
R154  49.9K  [R0402]  316.23 163.58 180 top
R155  49.9K  [R0402]  325.37 163.58 0 top
R156  49.9K  [R0402]  306.32 163.58 0 top
R157  4.99K  [R0805]  335.79 151.26 270 top
R158  100  [R0805]  333.76 153.42 270 top
R159  0  [R0402]  333.76 151.13 180 top
R160  4.99K  [R0805]  324.87 151.26 270 top
R161  100  [R0805]  326.9 153.42 270 top
R162  0  [R0402]  326.9 151.13 0 top
R163  4.99K  [R0805]  316.74 151.26 270 top
R164  100  [R0805]  314.71 153.42 270 top
R165  0  [R0402]  314.71 151.13 180 top
R166  4.99K  [R0805]  305.82 151.26 270 top
R167  100  [R0805]  307.85 153.42 270 top
R168  0  [R0402]  307.85 151.13 0 top
R169  4.99K  [R0805]  335.79 146.3 270 top
R170  4.99K  [R0805]  324.87 147.57 270 top
R171  4.99K  [R0805]  316.74 146.3 270 top
R172  4.99K  [R0805]  305.82 147.57 270 top
R173  49.9  [R0603]  331.09 143 270 top
R174  49.9  [R0603]  329.56 143 270 top
R175  49.9  [R0603]  312.04 143 270 top
R176  49.9  [R0603]  310.52 143 270 top
R177  475K  [R0603]  333.5 136.14 180 top
R178  475K  [R0603]  327.15 136.14 0 top
R179  475K  [R0603]  314.45 136.14 180 top
R180  475K  [R0603]  308.1 136.14 0 top
R181  49.9K  [R0402]  295.66 163.58 180 top
R182  49.9K  [R0402]  276.61 163.58 180 top
R183  49.9K  [R0402]  285.75 163.58 0 top
R184  49.9K  [R0402]  266.7 163.58 0 top
R185  4.99K  [R0805]  296.16 151.26 270 top
R186  100  [R0805]  294.13 153.42 270 top
R187  0  [R0402]  294.13 151.13 180 top
R188  4.99K  [R0805]  285.24 151.26 270 top
R189  100  [R0805]  287.27 153.42 270 top
R190  0  [R0402]  287.27 151.13 0 top
R191  4.99K  [R0805]  277.11 151.26 270 top
R192  100  [R0805]  275.08 153.42 270 top
R193  0  [R0402]  275.08 151.13 180 top
R194  4.99K  [R0805]  266.19 151.26 270 top
R195  100  [R0805]  268.22 153.42 270 top
R196  0  [R0402]  268.22 151.13 0 top
R197  4.99K  [R0805]  296.16 146.3 270 top
R198  4.99K  [R0805]  285.24 147.57 270 top
R199  4.99K  [R0805]  277.11 146.3 270 top
R200  4.99K  [R0805]  266.19 147.57 270 top
R201  49.9  [R0603]  291.47 143 270 top
R202  49.9  [R0603]  289.94 143 270 top
R203  49.9  [R0603]  272.42 143 270 top
R204  49.9  [R0603]  270.89 143 270 top
R205  475K  [R0603]  293.88 136.14 180 top
R206  475K  [R0603]  287.53 136.14 0 top
R207  475K  [R0603]  274.83 136.14 180 top
R208  475K  [R0603]  268.48 136.14 0 top
R209  49.9K  [R0402]  257.56 163.58 180 top
R210  49.9K  [R0402]  238.51 163.58 180 top
R211  49.9K  [R0402]  247.65 163.58 0 top
R212  49.9K  [R0402]  228.6 163.58 0 top
R213  4.99K  [R0805]  258.06 151.26 270 top
R214  100  [R0805]  256.03 153.42 270 top
R215  0  [R0402]  256.03 151.13 180 top
R216  4.99K  [R0805]  247.14 151.26 270 top
R217  100  [R0805]  249.17 153.42 270 top
R218  0  [R0402]  249.17 151.13 0 top
R219  4.99K  [R0805]  239.01 151.26 270 top
R220  100  [R0805]  236.98 153.42 270 top
R221  0  [R0402]  236.98 151.13 180 top
R222  4.99K  [R0805]  228.09 151.26 270 top
R223  100  [R0805]  230.12 153.42 270 top
R224  0  [R0402]  230.12 151.13 0 top
R225  4.99K  [R0805]  258.06 146.3 270 top
R226  4.99K  [R0805]  247.14 147.57 270 top
R227  4.99K  [R0805]  239.01 146.3 270 top
R228  4.99K  [R0805]  228.09 147.57 270 top
R229  49.9  [R0603]  253.36 143 270 top
R230  49.9  [R0603]  251.84 143 270 top
R231  49.9  [R0603]  234.31 143 270 top
R232  49.9  [R0603]  232.79 143 270 top
R233  475K  [R0603]  255.78 136.14 180 top
R234  475K  [R0603]  249.43 136.14 0 top
R235  475K  [R0603]  236.73 136.14 180 top
R236  475K  [R0603]  230.38 136.14 0 top
R237  49.9K  [R0402]  217.93 163.58 180 top
R238  49.9K  [R0402]  198.88 163.58 180 top
R239  49.9K  [R0402]  208.03 163.58 0 top
R240  49.9K  [R0402]  188.98 163.58 0 top
R241  4.99K  [R0805]  218.44 151.26 270 top
R242  100  [R0805]  216.41 153.42 270 top
R243  0  [R0402]  216.41 151.13 180 top
R244  4.99K  [R0805]  207.52 151.26 270 top
R245  100  [R0805]  209.55 153.42 270 top
R246  0  [R0402]  209.55 151.13 0 top
R247  4.99K  [R0805]  199.39 151.26 270 top
R248  100  [R0805]  197.36 153.42 270 top
R249  0  [R0402]  197.36 151.13 180 top
R250  4.99K  [R0805]  188.47 151.26 270 top
R251  100  [R0805]  190.5 153.42 270 top
R252  0  [R0402]  190.5 151.13 0 top
R253  4.99K  [R0805]  218.44 146.3 270 top
R254  4.99K  [R0805]  207.52 147.57 270 top
R255  4.99K  [R0805]  199.39 146.3 270 top
R256  4.99K  [R0805]  188.47 147.57 270 top
R257  49.9  [R0603]  213.74 143 270 top
R258  49.9  [R0603]  212.22 143 270 top
R259  49.9  [R0603]  194.69 143 270 top
R260  49.9  [R0603]  193.17 143 270 top
R261  475K  [R0603]  216.15 136.14 180 top
R262  475K  [R0603]  209.8 136.14 0 top
R263  475K  [R0603]  197.1 136.14 180 top
R264  475K  [R0603]  190.75 136.14 0 top
R265  33  [R0402]  127 101.07 90 top
R266  20K  [R0402]  128.14 101.07 270 top
R267  15K  [R0603]  33.02 20.37 0 top
R268  33  [R0402]  106.17 109.98 90 top
R269  10K  [R0402]  128.14 106.66 270 top
R270  33  [R0402]  107.31 109.98 90 top
R271  3.3K  [R0402]  125.22 106.66 270 top
R272  33  [R0402]  114.17 109.98 90 top
R273  3.3K  [R0402]  126.36 106.66 270 top
R274  33  [R0402]  111.89 109.98 90 top
R275  33  [R0402]  113.03 109.98 90 top
R276  33  [R0402]  110.74 109.98 90 top
R277  33  [R0402]  109.6 109.98 90 top
R278  10K  [R0402]  118.62 115.7 0 top
R279  33  [R0402]  108.46 109.98 90 top
R280  562  [R0402]  96.39 116.71 0 top
R281  0  [R0402]  96.39 115.62 0 top
R282  10K  [R0402]  118.62 117.47 0 top
R283  10K  [R0402]  118.62 118.62 0 top
R284  1K  [R0402]  104.65 109.98 270 top
R285  475  [R0805]  132.71 126.82 0 top
R286  475  [R0805]  132.71 128.85 0 top
R287  475  [R0805]  132.71 135.46 0 top
R288  475  [R0805]  132.71 137.49 0 top
R289  475  [R0805]  132.71 109.55 0 top
R290  475  [R0805]  132.71 111.58 0 top
R291  475  [R0805]  132.71 118.19 0 top
R292  475  [R0805]  132.71 120.22 0 top
R293  49.9K  [R0402]  147.32 126.19 90 top
R294  49.9K  [R0402]  147.32 129.49 270 top
R295  49.9K  [R0402]  147.32 134.82 90 top
R296  49.9K  [R0402]  147.32 138.13 270 top
R297  49.9K  [R0402]  147.32 108.92 90 top
R298  49.9K  [R0402]  147.32 112.22 270 top
R299  49.9K  [R0402]  147.32 117.55 90 top
R300  49.9K  [R0402]  147.32 120.85 270 top
R301  475  [R0805]  121.4 147.07 90 top
R302  475  [R0805]  119.37 147.07 90 top
R303  475  [R0805]  112.77 147.07 90 top
R304  475  [R0805]  110.73 147.07 90 top
R305  475  [R0805]  138.67 147.07 90 top
R306  475  [R0805]  136.64 147.07 90 top
R307  475  [R0805]  130.04 147.07 90 top
R308  475  [R0805]  128.01 147.07 90 top
R309  49.9K  [R0402]  122.04 161.67 180 top
R310  49.9K  [R0402]  118.73 161.67 0 top
R311  49.9K  [R0402]  113.4 161.67 180 top
R312  49.9K  [R0402]  110.1 161.67 0 top
R313  49.9K  [R0402]  139.31 161.67 180 top
R314  49.9K  [R0402]  136.01 161.67 0 top
R315  49.9K  [R0402]  130.67 161.67 180 top
R316  49.9K  [R0402]  127.37 161.67 0 top
R317  475  [R0805]  86.86 147.07 90 top
R318  475  [R0805]  84.83 147.07 90 top
R319  475  [R0805]  78.22 147.07 90 top
R320  475  [R0805]  76.19 147.07 90 top
R321  475  [R0805]  104.13 147.07 90 top
R322  475  [R0805]  102.1 147.07 90 top
R323  475  [R0805]  95.49 147.07 90 top
R324  475  [R0805]  93.46 147.07 90 top
R325  49.9K  [R0402]  87.49 161.67 180 top
R326  49.9K  [R0402]  84.19 161.67 0 top
R327  49.9K  [R0402]  78.86 161.67 180 top
R328  49.9K  [R0402]  75.55 161.67 0 top
R329  49.9K  [R0402]  104.76 161.67 180 top
R330  49.9K  [R0402]  101.46 161.67 0 top
R331  49.9K  [R0402]  96.13 161.67 180 top
R332  49.9K  [R0402]  92.83 161.67 0 top
R333  475  [R0805]  83.44 137.49 180 top
R334  475  [R0805]  83.44 135.46 180 top
R335  475  [R0805]  83.44 128.85 180 top
R336  475  [R0805]  83.44 126.82 180 top
R337  49.9K  [R0402]  68.83 138.13 270 top
R338  49.9K  [R0402]  68.83 134.82 90 top
R339  49.9K  [R0402]  68.83 129.49 270 top
R340  49.9K  [R0402]  68.83 126.19 90 top
R341  475  [R0805]  83.44 120.22 180 top
R342  475  [R0805]  83.44 118.19 180 top
R343  475  [R0805]  83.44 111.58 180 top
R344  475  [R0805]  83.44 109.55 180 top
R345  49.9K  [R0402]  68.83 120.85 270 top
R346  49.9K  [R0402]  68.83 117.55 90 top
R347  49.9K  [R0402]  68.83 112.22 270 top
R348  49.9K  [R0402]  68.83 108.92 90 top
R349  10K  [R0402]  295.32 103.87 180 bottom
R350  10K  [R0402]  305.35 103.87 180 bottom
R351  10K  [R0402]  217.6 103.87 180 bottom
R352  10K  [R0402]  227.63 103.87 180 bottom
R353  10K  [R0402]  116.54 95.66 0 bottom
R354  10K  [R0402]  134.07 95.66 0 bottom
R355  10K  [R0402]  118.28 98.14 180 bottom
R356  0  [R0402]  82.93 25.91 270 top
R357  0  [R0402]  68.83 25.91 270 top
R358  60.4  [R0402]  86.74 24 270 top
R359  60.4  [R0402]  88.01 24 90 top
R360  60.4  [R0402]  72.64 24 270 top
R361  60.4  [R0402]  73.91 24 90 top
R362  10K  [R0402]  68.94 8.13 0 bottom
R363  10K  [R0402]  68.94 14.86 0 bottom
R364  0  [R0402]  345.85 25.88 270 top
R365  0  [R0402]  331.75 25.88 270 top
R366  60.4  [R0402]  349.66 23.98 270 top
R367  60.4  [R0402]  350.93 23.98 90 top
R368  60.4  [R0402]  335.56 23.98 270 top
R369  60.4  [R0402]  336.83 23.98 90 top
R370  10K  [R0402]  331.85 8.1 0 bottom
R371  10K  [R0402]  331.85 14.83 0 bottom
R372  0  [R0402]  230.12 41.97 270 top
R373  0  [R0402]  231.27 41.97 270 top
R374  0  [R0402]  232.41 41.97 270 top
R375  0  [R0402]  233.55 41.97 270 top
R376  0  [R0402]  227.08 41.97 270 top
R377  0  [R0402]  228.22 41.97 270 top
R378  0  [R0402]  238.63 41.97 270 top
R379  0  [R0402]  239.78 41.97 270 top
R380  0  [R0402]  240.92 41.97 270 top
R381  0  [R0402]  242.06 41.97 270 top
R382  0  [R0402]  235.46 41.97 270 top
R383  0  [R0402]  236.6 41.97 270 top
R384  10K  [R0402]  226.57 38.54 0 top
R385  10K  [R0402]  234.95 38.54 0 top
R386  10K  [R0402]  228.73 38.54 180 top
R387  10K  [R0402]  237.11 38.54 180 top
R388  0  [R0402]  230.12 35.12 270 top
R389  0  [R0402]  231.27 35.12 270 top
R390  0  [R0402]  232.41 35.12 270 top
R391  0  [R0402]  233.55 35.12 270 top
R392  0  [R0402]  227.08 35.12 270 top
R393  0  [R0402]  228.22 35.12 270 top
R394  0  [R0402]  238.63 35.12 270 top
R395  0  [R0402]  239.78 35.12 270 top
R396  0  [R0402]  240.92 35.12 270 top
R397  0  [R0402]  242.06 35.12 270 top
R398  0  [R0402]  235.46 35.12 270 top
R399  0  [R0402]  236.6 35.12 270 top
R400  0  [R0402]  121.67 81.47 0 bottom
R401  0  [R0402]  121.67 82.99 0 bottom
R402  0  [R0402]  129.03 83.5 180 bottom
R403  0  [R0402]  129.03 81.98 180 bottom
R404  0  [R0402]  138.18 81.47 0 bottom
R405  0  [R0402]  138.18 82.99 0 bottom
R406  0  [R0402]  145.54 83.5 180 bottom
R407  0  [R0402]  145.54 81.98 180 bottom
R408  10K  [R0402]  129.03 80.45 0 bottom
R409  10K  [R0402]  145.54 80.45 0 bottom
R410  10K  [R0402]  256.03 80.45 0 bottom
R411  10K  [R0402]  272.54 80.45 0 bottom
R412  0  [R0402]  248.67 81.47 180 bottom
R413  0  [R0402]  248.67 82.99 180 bottom
R414  0  [R0402]  256.03 83.5 0 bottom
R415  0  [R0402]  256.03 81.98 0 bottom
R416  0  [R0402]  265.18 81.47 180 bottom
R417  0  [R0402]  265.18 82.99 180 bottom
R418  0  [R0402]  272.54 83.5 0 bottom
R419  0  [R0402]  272.54 81.98 0 bottom
R420  10  [R0402]  24.51 100.58 270 top
R421  10  [R0402]  26.04 100.58 270 top
R422  10  [R0402]  27.56 100.58 270 top
R423  10  [R0402]  29.08 100.58 270 top
R424  10  [R0402]  30.61 100.58 270 top
R425  10  [R0402]  32.13 100.58 270 top
R426  10  [R0402]  252.48 105.66 270 top
R427  10  [R0402]  254 105.66 270 top
R428  10  [R0402]  255.52 105.66 270 top
R429  10  [R0402]  257.05 105.66 270 top
R430  10  [R0402]  258.57 105.66 270 top
R431  10  [R0402]  260.1 105.66 270 top
R432  10K  [R0402]  191.13 99.31 270 top
R433  10K  [R0402]  335.03 99.31 270 top
R434  10K  [R0402]  191.13 91.44 270 top
R435  10K  [R0402]  335.03 91.44 270 top
R436  10K  [R0402]  191.13 107.19 270 top
R437  10K  [R0402]  335.03 107.19 270 top
R438  18.2K  [R0402]  396.49 151 0 top
R439  18.2K  [R0402]  396.49 105.41 0 top
R440  10K  [R0402]  401.07 156.08 180 top
R441  100K  [R0402]  405 107.44 0 top
R442  100K  [R0402]  405 153.04 0 top
R443  768K  [R0402]  401.07 105.41 180 top
R444  84.5K  [R0402]  401.07 151 180 top
R445  1MEG  [R0402_A]  405.51 105.41 90 top
R446  1MEG  [R0402_A]  405.51 151 90 top
R447  18.2K  [R0402]  396.49 128.27 0 top
R448  18.2K  [R0402]  396.49 171.45 0 top
R449  10  [R0402]  128.27 90.61 180 top
R450  10  [R0402]  128.27 89.09 180 top
R451  100K  [R0402]  405 130.3 0 top
R452  100K  [R0402]  405 173.48 0 top
R453  309K  [R0402]  401.07 128.27 180 top
R454  187K  [R0402]  401.07 171.45 180 top
R455  1MEG  [R0402_A]  405.51 128.27 90 top
R456  1MEG  [R0402_A]  405.51 171.45 90 top
R457  10  [R0402]  255.27 89.09 180 top
R458  10  [R0402]  255.27 90.61 180 top
R459  10K  [R0402]  368.81 171.45 0 top
R460  0  [R0201]  368.94 173.99 180 top
R461  0  [R0201]  368.94 168.91 180 top
R462  3K  [R0402]  219.01 90.11 270 top
R463  5.62K  [R0402]  209.42 15.28 0 top
R464  10K  [R0201]  197.74 36.89 0 top
R465  10K  [R0201]  207.14 34.35 0 top
R466  10K  [R0201]  197.74 35.62 0 top
R467  10K  [R0201]  197.74 34.35 0 top
R468  3.32K  [R0402]  199.9 22.8 0 top
R469  10K  [R0201]  207.14 35.62 180 top
R470  10K  [R0201]  198.73 14.77 180 top
R471  3.32K  [R0402]  199.9 23.94 0 top
R472  33  [R0402]  201.93 23.94 0 top
R473  10K  [R0201]  203.39 27.24 0 top
